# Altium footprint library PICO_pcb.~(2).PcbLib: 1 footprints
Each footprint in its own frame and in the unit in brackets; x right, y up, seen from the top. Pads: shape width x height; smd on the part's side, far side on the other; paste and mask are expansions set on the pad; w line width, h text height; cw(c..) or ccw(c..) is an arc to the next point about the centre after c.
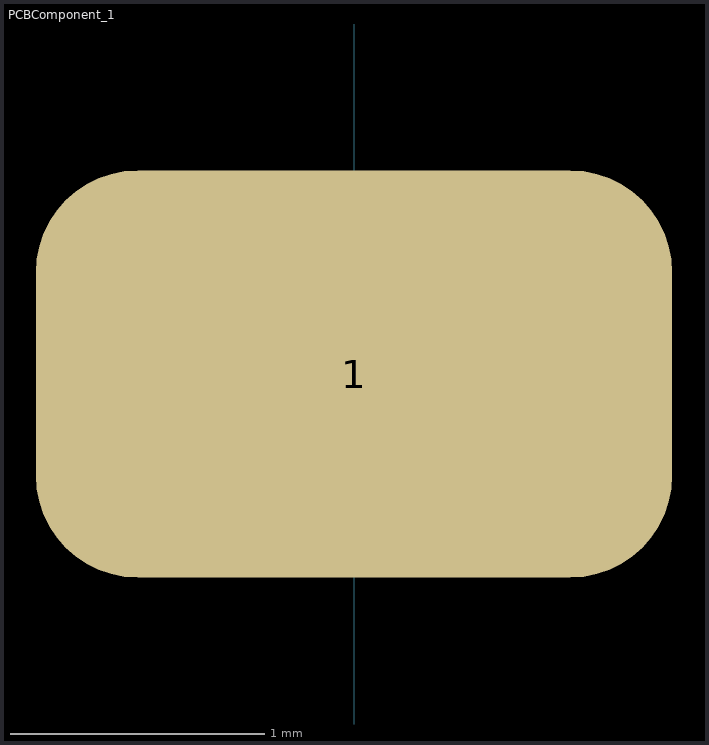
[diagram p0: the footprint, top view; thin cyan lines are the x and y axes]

## PCBComponent_1 [mm]
pads (1):
  rrect50% 2.5x1.6 smd: 1(0,5.08)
